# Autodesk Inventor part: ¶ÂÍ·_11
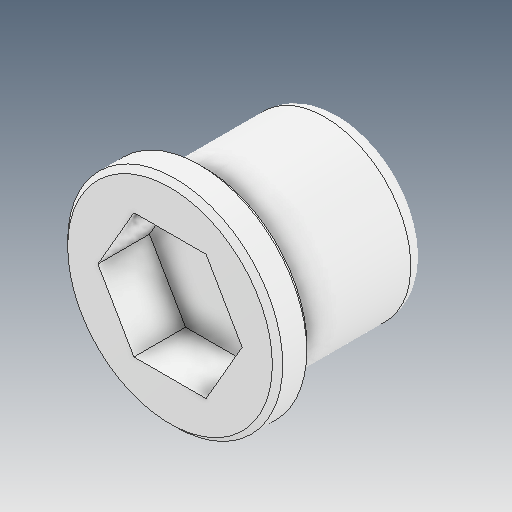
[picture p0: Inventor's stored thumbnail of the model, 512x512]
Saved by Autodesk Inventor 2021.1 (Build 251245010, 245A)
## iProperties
Created: 2021-06
Part Number: ¶ÂÍ·_11
Material: Ogólny
Document SubType Name: Modeling
Designer: user
Density: 1 g/cm^3
Appearance: Domyślna
Author: user
Revision Number: ÈÎºÎ
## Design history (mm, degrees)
feature "ÊäÈë1"
node "Bryła1"
